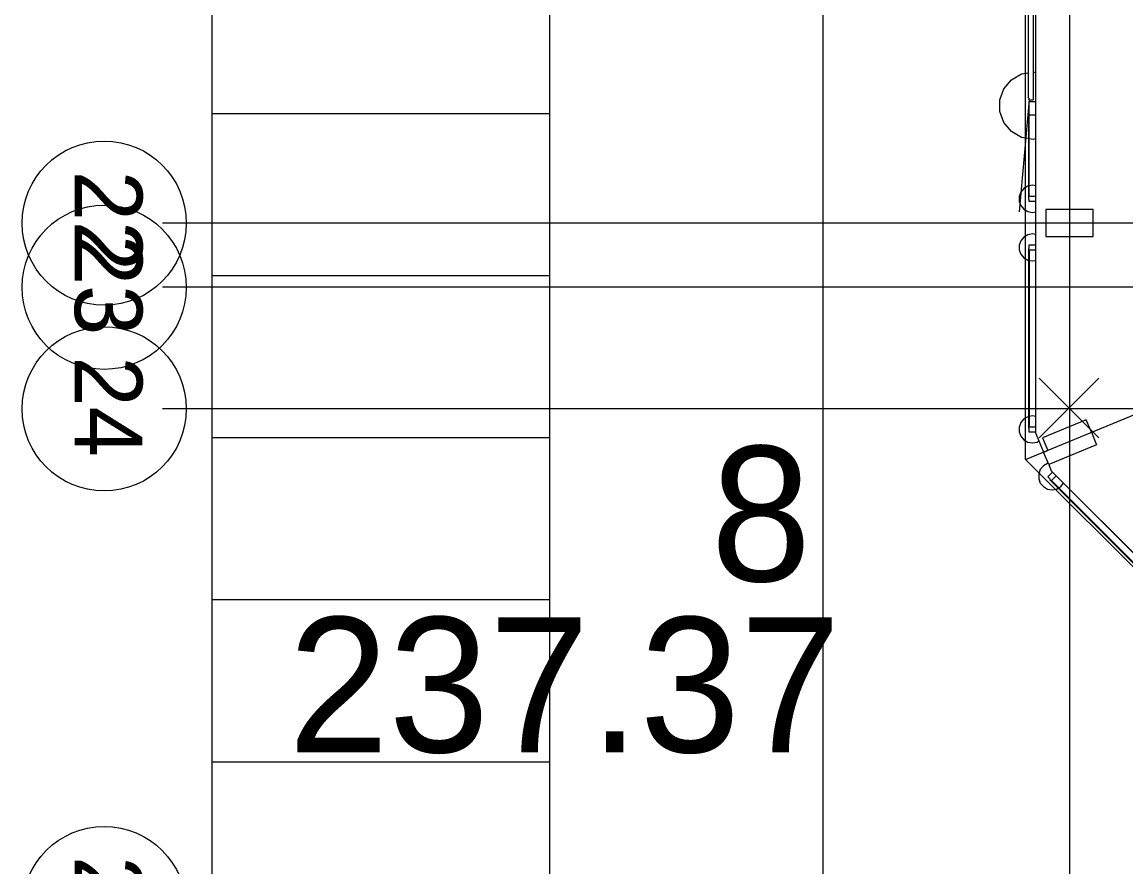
# Model space of a CAD drawing. Extents: x -264165 to -263575, y -1242333 to -1242036.
# Drawn here: x -263923.9 to -263907.56, y -1242233.41 to -1242220.9 of the extents above; entities that cross this region are included whole.
import ezdxf

# ---------------------------------------------------------------- set-up
doc = ezdxf.new("R2010")
doc.units = 0
for name, color, linetype in [('KFA_BODY_VYTYCOVAK', 7, 'Continuous'), ('KFA_HESCON_OSI_STAVBY', 7, 'Continuous'), ('KFA_SITUACIA_DRS_VYTYCOVAK_SEDA', 7, 'Continuous')]:
    doc.layers.add(name, color=color, linetype=linetype)

msp = doc.modelspace()

# ---------------------------------------------------------------- linework, layer by layer
at = {"layer": 'KFA_BODY_VYTYCOVAK'}
for p, q in [((-263908.842, -1242227.062), (-263907.958, -1242226.178)), ((-263907.958, -1242227.062), (-263908.842, -1242226.178))]:
    msp.add_line(p, q, dxfattribs=at)
at = {"layer": 'KFA_HESCON_OSI_STAVBY'}
for p, q in [((-263908.393, -1242080.447), (-263908.393, -1242248.737)), ((-263909.043, -1242227.382), (-263885.015, -1242217.43)), ((-263787.486, -1242223.882), (-263921.823, -1242223.882)), ((-263787.486, -1242224.832), (-263921.823, -1242224.832)), ((-263787.486, -1242226.632), (-263921.823, -1242226.632))]:
    msp.add_line(p, q, dxfattribs=at)
for centre in [(-263922.688, -1242223.882), (-263922.688, -1242224.832), (-263922.688, -1242226.632), (-263922.688, -1242234.032)]:
    msp.add_circle(centre, 1.216, dxfattribs=at)
at = {"layer": 'KFA_SITUACIA_DRS_VYTYCOVAK_SEDA'}
for p, q in [((-263921.093, -1242087.308), (-263921.093, -1242241.458)), ((-263912.043, -1242228.625), (-263912.043, -1242100.14)), ((-263916.093, -1242187.557), (-263916.093, -1242241.458)), ((-263909.043, -1242227.382), (-263909.043, -1242196.333)), ((-263908.893, -1242223.882), (-263908.893, -1242216.882)), ((-263908.893, -1242223.882), (-263908.893, -1242216.882)), ((-263908.893, -1242226.995), (-263908.893, -1242216.882)), ((-263908.893, -1242226.995), (-263908.893, -1242216.882)), ((-263909.003, -1242222.032), (-263909.003, -1242220.423)), ((-263909.003, -1242222.032), (-263909.003, -1242220.423)), ((-263908.933, -1242220.392), (-263908.933, -1242222.057)), ((-263908.933, -1242220.392), (-263908.933, -1242222.057)), ((-263909.254, -1242221.759), (-263909.104, -1242221.672)), ((-263909.254, -1242221.759), (-263909.104, -1242221.672)), ((-263909.104, -1242221.672), (-263909.003, -1242221.655)), ((-263909.104, -1242221.672), (-263909.003, -1242221.655)), ((-263908.933, -1242221.642), (-263908.893, -1242221.649)), ((-263908.933, -1242221.642), (-263908.893, -1242221.649)), ((-263909.366, -1242221.892), (-263909.254, -1242221.759)), ((-263909.366, -1242221.892), (-263909.254, -1242221.759)), ((-263909.425, -1242222.055), (-263909.366, -1242221.892)), ((-263909.425, -1242222.055), (-263909.366, -1242221.892)), ((-263909.425, -1242222.229), (-263909.425, -1242222.055)), ((-263909.425, -1242222.229), (-263909.425, -1242222.055)), ((-263908.993, -1242222.057), (-263909.138, -1242223.716)), ((-263908.993, -1242222.057), (-263909.138, -1242223.716)), ((-263909.003, -1242222.032), (-263908.993, -1242222.032)), ((-263909.003, -1242222.032), (-263908.993, -1242222.032)), ((-263908.993, -1242222.057), (-263908.993, -1242222.032)), ((-263908.993, -1242222.057), (-263908.993, -1242222.032)), ((-263908.993, -1242222.057), (-263908.933, -1242222.057)), ((-263908.993, -1242222.057), (-263908.933, -1242222.057)), ((-263908.993, -1242222.202), (-263908.993, -1242222.082)), ((-263908.993, -1242222.202), (-263908.993, -1242222.082)), ((-263908.993, -1242222.082), (-263908.893, -1242222.082)), ((-263908.993, -1242222.082), (-263908.893, -1242222.082)), ((-263921.093, -1242222.257), (-263916.093, -1242222.257)), ((-263909.366, -1242222.392), (-263909.425, -1242222.229)), ((-263909.366, -1242222.392), (-263909.425, -1242222.229)), ((-263908.993, -1242222.223), (-263909.003, -1242222.223)), ((-263908.993, -1242222.223), (-263909.003, -1242222.223)), ((-263909.003, -1242222.223), (-263909.003, -1242223.532)), ((-263909.003, -1242222.223), (-263909.003, -1242223.532)), ((-263908.993, -1242222.282), (-263908.993, -1242222.202)), ((-263908.993, -1242222.282), (-263908.993, -1242222.202)), ((-263908.993, -1242223.482), (-263908.993, -1242222.223)), ((-263908.993, -1242223.482), (-263908.993, -1242222.223)), ((-263908.893, -1242222.282), (-263908.993, -1242222.282)), ((-263908.893, -1242222.282), (-263908.993, -1242222.282)), ((-263909.254, -1242222.525), (-263909.366, -1242222.392)), ((-263909.254, -1242222.525), (-263909.366, -1242222.392)), ((-263909.104, -1242222.612), (-263909.254, -1242222.525)), ((-263909.104, -1242222.612), (-263909.254, -1242222.525)), ((-263909.003, -1242222.63), (-263909.104, -1242222.612)), ((-263909.003, -1242222.63), (-263909.104, -1242222.612)), ((-263908.933, -1242222.642), (-263908.993, -1242222.632)), ((-263908.933, -1242222.642), (-263908.993, -1242222.632)), ((-263908.893, -1242222.635), (-263908.933, -1242222.642)), ((-263908.893, -1242222.635), (-263908.933, -1242222.642)), ((-263909.116, -1242223.422), (-263909.14, -1242223.487)), ((-263909.116, -1242223.422), (-263909.14, -1242223.487)), ((-263909.071, -1242223.369), (-263909.116, -1242223.422)), ((-263909.071, -1242223.369), (-263909.116, -1242223.422)), ((-263909.011, -1242223.334), (-263909.071, -1242223.369)), ((-263909.011, -1242223.334), (-263909.071, -1242223.369)), ((-263909.003, -1242223.333), (-263909.011, -1242223.334)), ((-263909.003, -1242223.333), (-263909.011, -1242223.334)), ((-263908.943, -1242223.322), (-263908.993, -1242223.331)), ((-263908.943, -1242223.322), (-263908.993, -1242223.331)), ((-263908.993, -1242223.482), (-263908.893, -1242223.482)), ((-263908.993, -1242223.482), (-263908.893, -1242223.482)), ((-263908.893, -1242223.331), (-263908.943, -1242223.322)), ((-263908.893, -1242223.331), (-263908.943, -1242223.322)), ((-263909.14, -1242223.487), (-263909.14, -1242223.557)), ((-263909.14, -1242223.487), (-263909.14, -1242223.557)), ((-263909.14, -1242223.557), (-263909.116, -1242223.622)), ((-263909.14, -1242223.557), (-263909.116, -1242223.622)), ((-263909.116, -1242223.622), (-263909.071, -1242223.675)), ((-263909.116, -1242223.622), (-263909.071, -1242223.675)), ((-263909.003, -1242223.532), (-263908.993, -1242223.532)), ((-263909.003, -1242223.532), (-263908.993, -1242223.532)), ((-263908.993, -1242223.562), (-263908.993, -1242223.532)), ((-263908.993, -1242223.562), (-263908.993, -1242223.532)), ((-263908.893, -1242223.562), (-263908.993, -1242223.562)), ((-263908.893, -1242223.562), (-263908.993, -1242223.562)), ((-263909.071, -1242223.675), (-263909.011, -1242223.71)), ((-263909.071, -1242223.675), (-263909.011, -1242223.71)), ((-263909.011, -1242223.71), (-263908.943, -1242223.722)), ((-263909.011, -1242223.71), (-263908.943, -1242223.722)), ((-263908.943, -1242223.722), (-263908.893, -1242223.713)), ((-263908.943, -1242223.722), (-263908.893, -1242223.713)), ((-263908.743, -1242223.682), (-263908.743, -1242223.882)), ((-263908.743, -1242223.682), (-263908.743, -1242223.882)), ((-263908.743, -1242223.682), (-263908.743, -1242224.082)), ((-263908.743, -1242223.682), (-263908.743, -1242224.082)), ((-263908.043, -1242223.682), (-263908.743, -1242223.682)), ((-263908.043, -1242223.682), (-263908.743, -1242223.682)), ((-263908.043, -1242224.082), (-263908.043, -1242223.682)), ((-263908.043, -1242224.082), (-263908.043, -1242223.682)), ((-263908.893, -1242226.995), (-263908.893, -1242223.882)), ((-263908.893, -1242226.995), (-263908.893, -1242223.882)), ((-263908.743, -1242223.882), (-263908.743, -1242224.082)), ((-263908.743, -1242223.882), (-263908.743, -1242224.082)), ((-263909.071, -1242224.089), (-263909.116, -1242224.142)), ((-263909.071, -1242224.089), (-263909.116, -1242224.142)), ((-263909.011, -1242224.054), (-263909.071, -1242224.089)), ((-263909.011, -1242224.054), (-263909.071, -1242224.089)), ((-263908.943, -1242224.042), (-263909.011, -1242224.054)), ((-263908.943, -1242224.042), (-263909.011, -1242224.054)), ((-263908.893, -1242224.051), (-263908.943, -1242224.042)), ((-263908.893, -1242224.051), (-263908.943, -1242224.042)), ((-263908.743, -1242224.082), (-263908.043, -1242224.082)), ((-263908.743, -1242224.082), (-263908.043, -1242224.082)), ((-263909.116, -1242224.142), (-263909.14, -1242224.207)), ((-263909.116, -1242224.142), (-263909.14, -1242224.207)), ((-263909.14, -1242224.207), (-263909.14, -1242224.277)), ((-263909.14, -1242224.207), (-263909.14, -1242224.277)), ((-263909.14, -1242224.277), (-263909.116, -1242224.342)), ((-263909.14, -1242224.277), (-263909.116, -1242224.342)), ((-263908.993, -1242224.259), (-263909.003, -1242224.259)), ((-263908.993, -1242224.259), (-263909.003, -1242224.259)), ((-263909.003, -1242224.259), (-263909.003, -1242226.918)), ((-263909.003, -1242224.259), (-263909.003, -1242226.918)), ((-263908.993, -1242224.259), (-263908.993, -1242224.202)), ((-263908.993, -1242224.259), (-263908.993, -1242224.202)), ((-263908.993, -1242224.202), (-263908.893, -1242224.202)), ((-263908.993, -1242224.202), (-263908.893, -1242224.202)), ((-263908.993, -1242224.282), (-263908.993, -1242226.896)), ((-263908.993, -1242224.282), (-263908.993, -1242226.896)), ((-263908.893, -1242224.282), (-263908.993, -1242224.282)), ((-263908.893, -1242224.282), (-263908.993, -1242224.282)), ((-263909.116, -1242224.342), (-263909.071, -1242224.395)), ((-263909.116, -1242224.342), (-263909.071, -1242224.395)), ((-263909.071, -1242224.395), (-263909.011, -1242224.43)), ((-263909.071, -1242224.395), (-263909.011, -1242224.43)), ((-263909.011, -1242224.43), (-263909.003, -1242224.432)), ((-263909.011, -1242224.43), (-263909.003, -1242224.432)), ((-263908.993, -1242224.433), (-263908.943, -1242224.442)), ((-263908.993, -1242224.433), (-263908.943, -1242224.442)), ((-263908.943, -1242224.442), (-263908.893, -1242224.433)), ((-263908.943, -1242224.442), (-263908.893, -1242224.433)), ((-263921.093, -1242224.657), (-263916.093, -1242224.657)), ((-263909.011, -1242226.748), (-263909.071, -1242226.782)), ((-263909.011, -1242226.748), (-263909.071, -1242226.782)), ((-263909.003, -1242226.746), (-263909.011, -1242226.748)), ((-263909.003, -1242226.746), (-263909.011, -1242226.748)), ((-263908.943, -1242226.736), (-263908.993, -1242226.744)), ((-263908.943, -1242226.736), (-263908.993, -1242226.744)), ((-263908.893, -1242226.744), (-263908.943, -1242226.736)), ((-263908.893, -1242226.744), (-263908.943, -1242226.736)), ((-263909.116, -1242226.836), (-263909.14, -1242226.901)), ((-263909.116, -1242226.836), (-263909.14, -1242226.901)), ((-263909.14, -1242226.901), (-263909.14, -1242226.97)), ((-263909.14, -1242226.901), (-263909.14, -1242226.97)), ((-263909.071, -1242226.782), (-263909.116, -1242226.836)), ((-263909.071, -1242226.782), (-263909.116, -1242226.836)), ((-263908.993, -1242226.896), (-263908.893, -1242226.896)), ((-263908.993, -1242226.896), (-263908.893, -1242226.896)), ((-263908.146, -1242226.794), (-263908.793, -1242227.062)), ((-263908.146, -1242226.794), (-263908.793, -1242227.062)), ((-263908.069, -1242226.979), (-263908.146, -1242226.794)), ((-263908.069, -1242226.979), (-263908.146, -1242226.794)), ((-263921.093, -1242227.057), (-263916.093, -1242227.057)), ((-263909.14, -1242226.97), (-263909.116, -1242227.036)), ((-263909.14, -1242226.97), (-263909.116, -1242227.036)), ((-263909.116, -1242227.036), (-263909.071, -1242227.089)), ((-263909.116, -1242227.036), (-263909.071, -1242227.089)), ((-263908.993, -1242226.918), (-263909.003, -1242226.918)), ((-263908.993, -1242226.918), (-263909.003, -1242226.918)), ((-263908.993, -1242226.976), (-263908.993, -1242226.918)), ((-263908.993, -1242226.976), (-263908.993, -1242226.918)), ((-263908.893, -1242226.976), (-263908.993, -1242226.976)), ((-263908.893, -1242226.976), (-263908.993, -1242226.976)), ((-263908.893, -1242226.995), (-263908.778, -1242227.273)), ((-263908.893, -1242226.995), (-263908.778, -1242227.273)), ((-263908.793, -1242227.062), (-263908.716, -1242227.247)), ((-263908.793, -1242227.062), (-263908.716, -1242227.247)), ((-263908.069, -1242226.979), (-263907.993, -1242227.164)), ((-263908.069, -1242226.979), (-263907.993, -1242227.164)), ((-263909.071, -1242227.089), (-263909.011, -1242227.123)), ((-263909.071, -1242227.089), (-263909.011, -1242227.123)), ((-263909.011, -1242227.123), (-263908.943, -1242227.136)), ((-263909.011, -1242227.123), (-263908.943, -1242227.136)), ((-263908.943, -1242227.136), (-263908.874, -1242227.123)), ((-263908.943, -1242227.136), (-263908.874, -1242227.123)), ((-263908.874, -1242227.123), (-263908.846, -1242227.107)), ((-263908.874, -1242227.123), (-263908.846, -1242227.107)), ((-263907.993, -1242227.164), (-263908.701, -1242227.457)), ((-263907.993, -1242227.164), (-263908.701, -1242227.457)), ((-263894.968, -1242241.457), (-263909.043, -1242227.382)), ((-263908.778, -1242227.273), (-263908.716, -1242227.247)), ((-263908.778, -1242227.273), (-263908.716, -1242227.247)), ((-263908.701, -1242227.457), (-263908.778, -1242227.273)), ((-263908.701, -1242227.457), (-263908.778, -1242227.273)), ((-263908.826, -1242227.531), (-263908.849, -1242227.596)), ((-263908.826, -1242227.531), (-263908.849, -1242227.596)), ((-263908.781, -1242227.478), (-263908.826, -1242227.531)), ((-263908.781, -1242227.478), (-263908.826, -1242227.531)), ((-263908.721, -1242227.443), (-263908.781, -1242227.478)), ((-263908.721, -1242227.443), (-263908.781, -1242227.478)), ((-263908.708, -1242227.441), (-263908.721, -1242227.443)), ((-263908.708, -1242227.441), (-263908.721, -1242227.443)), ((-263908.716, -1242227.638), (-263908.645, -1242227.567)), ((-263908.716, -1242227.638), (-263908.645, -1242227.567)), ((-263908.701, -1242227.457), (-263908.663, -1242227.55)), ((-263908.701, -1242227.457), (-263908.663, -1242227.55)), ((-263908.663, -1242227.55), (-263908.645, -1242227.567)), ((-263908.663, -1242227.55), (-263908.645, -1242227.567)), ((-263904.374, -1242231.839), (-263908.663, -1242227.55)), ((-263904.374, -1242231.839), (-263908.663, -1242227.55)), ((-263908.663, -1242227.55), (-263904.374, -1242231.839)), ((-263908.663, -1242227.55), (-263904.374, -1242231.839)), ((-263908.645, -1242227.567), (-263908.589, -1242227.624)), ((-263908.645, -1242227.567), (-263908.589, -1242227.624)), ((-263908.849, -1242227.596), (-263908.849, -1242227.666)), ((-263908.849, -1242227.596), (-263908.849, -1242227.666)), ((-263908.849, -1242227.666), (-263908.826, -1242227.731)), ((-263908.849, -1242227.666), (-263908.826, -1242227.731)), ((-263908.826, -1242227.731), (-263908.781, -1242227.784)), ((-263908.826, -1242227.731), (-263908.781, -1242227.784)), ((-263908.68, -1242227.674), (-263908.716, -1242227.638)), ((-263908.68, -1242227.674), (-263908.716, -1242227.638)), ((-263908.68, -1242227.674), (-263908.687, -1242227.681)), ((-263908.68, -1242227.674), (-263908.687, -1242227.681)), ((-263907.373, -1242228.996), (-263908.687, -1242227.681)), ((-263907.373, -1242228.996), (-263908.687, -1242227.681)), ((-263908.589, -1242227.624), (-263908.66, -1242227.695)), ((-263908.589, -1242227.624), (-263908.66, -1242227.695)), ((-263908.66, -1242227.695), (-263907.387, -1242228.968)), ((-263908.66, -1242227.695), (-263907.387, -1242228.968)), ((-263908.589, -1242227.624), (-263907.316, -1242228.897)), ((-263908.589, -1242227.624), (-263907.316, -1242228.897)), ((-263908.524, -1242227.784), (-263908.48, -1242227.732)), ((-263908.524, -1242227.784), (-263908.48, -1242227.732)), ((-263908.781, -1242227.784), (-263908.721, -1242227.819)), ((-263908.781, -1242227.784), (-263908.721, -1242227.819)), ((-263908.721, -1242227.819), (-263908.652, -1242227.831)), ((-263908.721, -1242227.819), (-263908.652, -1242227.831)), ((-263908.652, -1242227.831), (-263908.584, -1242227.819)), ((-263908.652, -1242227.831), (-263908.584, -1242227.819)), ((-263908.584, -1242227.819), (-263908.562, -1242227.806)), ((-263908.584, -1242227.819), (-263908.562, -1242227.806)), ((-263908.553, -1242227.801), (-263908.524, -1242227.784)), ((-263908.553, -1242227.801), (-263908.524, -1242227.784)), ((-263912.043, -1242238.458), (-263912.043, -1242228.625)), ((-263921.093, -1242229.457), (-263916.093, -1242229.457)), ((-263921.093, -1242231.857), (-263916.093, -1242231.857))]:
    msp.add_line(p, q, dxfattribs=at)

# ---------------------------------------------------------------- texts
at = {"layer": 'KFA_BODY_VYTYCOVAK'}
for s, p in [('8', (-263913.706, -1242229.184)), ('237.37', (-263919.963, -1242231.717))]:
    msp.add_text(s, height=2, dxfattribs=at).set_placement(p)
at = {"layer": 'KFA_HESCON_OSI_STAVBY'}
for s, p in [('22', (-263923.123, -1242223.105)), ('23', (-263923.123, -1242224.055)), ('24', (-263923.123, -1242225.855)), ('25', (-263923.123, -1242233.255))]:
    msp.add_text(s, height=1, rotation=270, dxfattribs=at).set_placement(p)

doc.saveas('drawing.dxf')
